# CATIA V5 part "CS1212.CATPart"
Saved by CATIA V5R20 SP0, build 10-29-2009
Part number: CS1212
Revision: 4
Definition: design
Nomenclature: CS1212
Source: made
Description: NOT SPECIFIED
Bounding box of the stored display mesh (mm): x -11.818 to 12, y -12 to 12, z -22 to 6
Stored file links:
  C:\Users\Raffaele\Desktop\3D X SITO CF\BOLEX\20-TILTED COLUMN SUPPORT\CS1212.CATPart
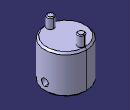
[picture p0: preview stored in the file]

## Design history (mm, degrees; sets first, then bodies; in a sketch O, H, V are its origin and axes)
Body1 "MANIFOLD_SOLID_BREP #683" (main body)
  Solid1: solid without history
